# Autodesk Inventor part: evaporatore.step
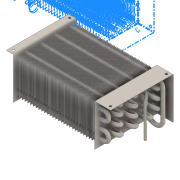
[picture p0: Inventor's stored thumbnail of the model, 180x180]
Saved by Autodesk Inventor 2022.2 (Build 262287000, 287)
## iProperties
Created: 2023-11
Part Number: evaporatore.step
Material: Rame
Document SubType Name: Modeling
Designer: 18907419
Density: 8.94 g/cm^3
Appearance: Rame - Lucidato
Author: 18907419
Revision Number: ANY
Sending System: SolidWorks 2018
Last Author: v.buzunov
Last Saved: 2023-11-30
Material: 4 0.9
MaterialUser: 12
Толщина: 1.2
Weight: 0.0
Nomenclature: _________________
Part Number: _________________
Source: NOT_KNOWN
Definition: UNKNOWN
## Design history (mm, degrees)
feature "evaporatore.STEP"
node "Solido1"
